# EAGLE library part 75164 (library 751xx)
75xxx DEVICE
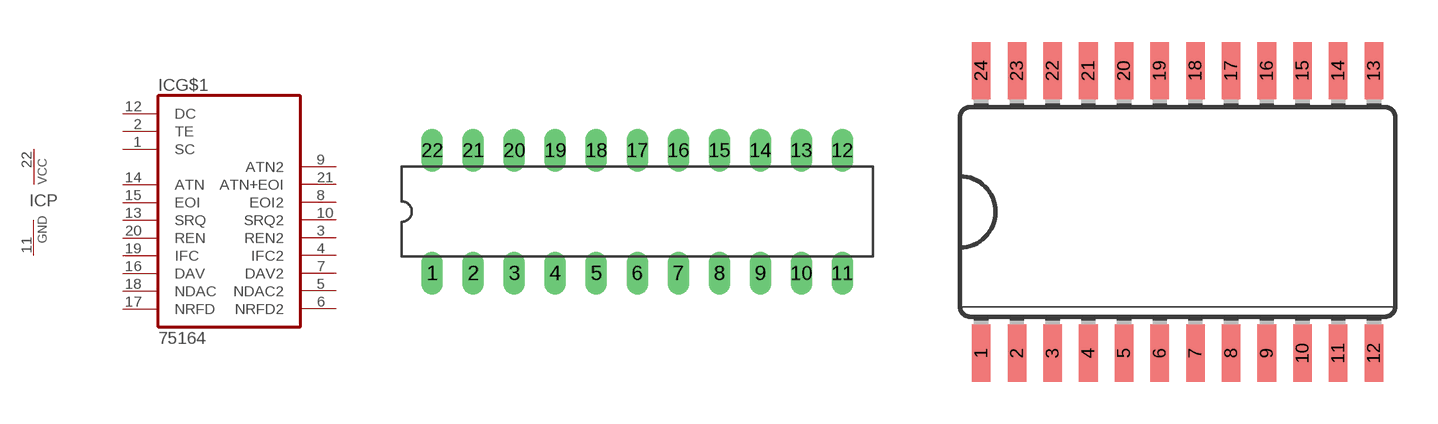
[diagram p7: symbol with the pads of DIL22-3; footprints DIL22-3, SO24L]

Designator prefix IC; gates G$1=75164 P=PWRN

## 75164P  [DIL22-3]
1  G$1:SC  in
2  G$1:TE  in
3  G$1:REN2
4  G$1:IFC2
5  G$1:NDAC2
6  G$1:NRFD2
7  G$1:DAV2
8  G$1:EOI2
9  G$1:ATN2
10  G$1:SRQ2
11  P:GND  pwr
12  G$1:DC  in
13  G$1:SRQ
14  G$1:ATN
15  G$1:EOI
16  G$1:DAV
17  G$1:NRFD
18  G$1:NDAC
19  G$1:IFC
20  G$1:REN
21  G$1:ATN+EOI
22  P:VCC  pwr

## 75164SO  [SO24L]
Pads as for DIL22-3

## Footprint DIL22-3 (pad centres in mm)
Dual In Line Package 0.3 inch
drill 0.813 long: 1 -12.7,-3.81; 2 -10.16,-3.81; 3 -7.62,-3.81; 4 -5.08,-3.81; 5 -2.54,-3.81; 6 0,-3.81; 7 2.54,-3.81; 8 5.08,-3.81; 9 7.62,-3.81; 10 10.16,-3.81; 11 12.7,-3.81; 12 12.7,3.81; 13 10.16,3.81; 14 7.62,3.81; 15 5.08,3.81; 16 2.54,3.81; 17 0,3.81; 18 -2.54,3.81; 19 -5.08,3.81; 20 -7.62,3.81; 21 -10.16,3.81; 22 -12.7,3.81

## Footprint SO24L (pad centres in mm)
Small Outline package large
smd 0.66 x 2.032: 1 -6.985,-5.029; 2 -5.715,-5.029; 3 -4.445,-5.029; 4 -3.175,-5.029; 5 -1.905,-5.029; 6 -0.635,-5.029; 7 0.635,-5.029; 8 1.905,-5.029; 9 3.175,-5.029; 10 4.445,-5.029; 11 5.715,-5.029; 12 6.985,-5.029; 13 6.985,5.029; 14 5.715,5.029; 15 4.445,5.029; 16 3.175,5.029; 17 1.905,5.029; 18 0.635,5.029; 19 -0.635,5.029; 20 -1.905,5.029; 21 -3.175,5.029; 22 -4.445,5.029; 23 -5.715,5.029; 24 -6.985,5.029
